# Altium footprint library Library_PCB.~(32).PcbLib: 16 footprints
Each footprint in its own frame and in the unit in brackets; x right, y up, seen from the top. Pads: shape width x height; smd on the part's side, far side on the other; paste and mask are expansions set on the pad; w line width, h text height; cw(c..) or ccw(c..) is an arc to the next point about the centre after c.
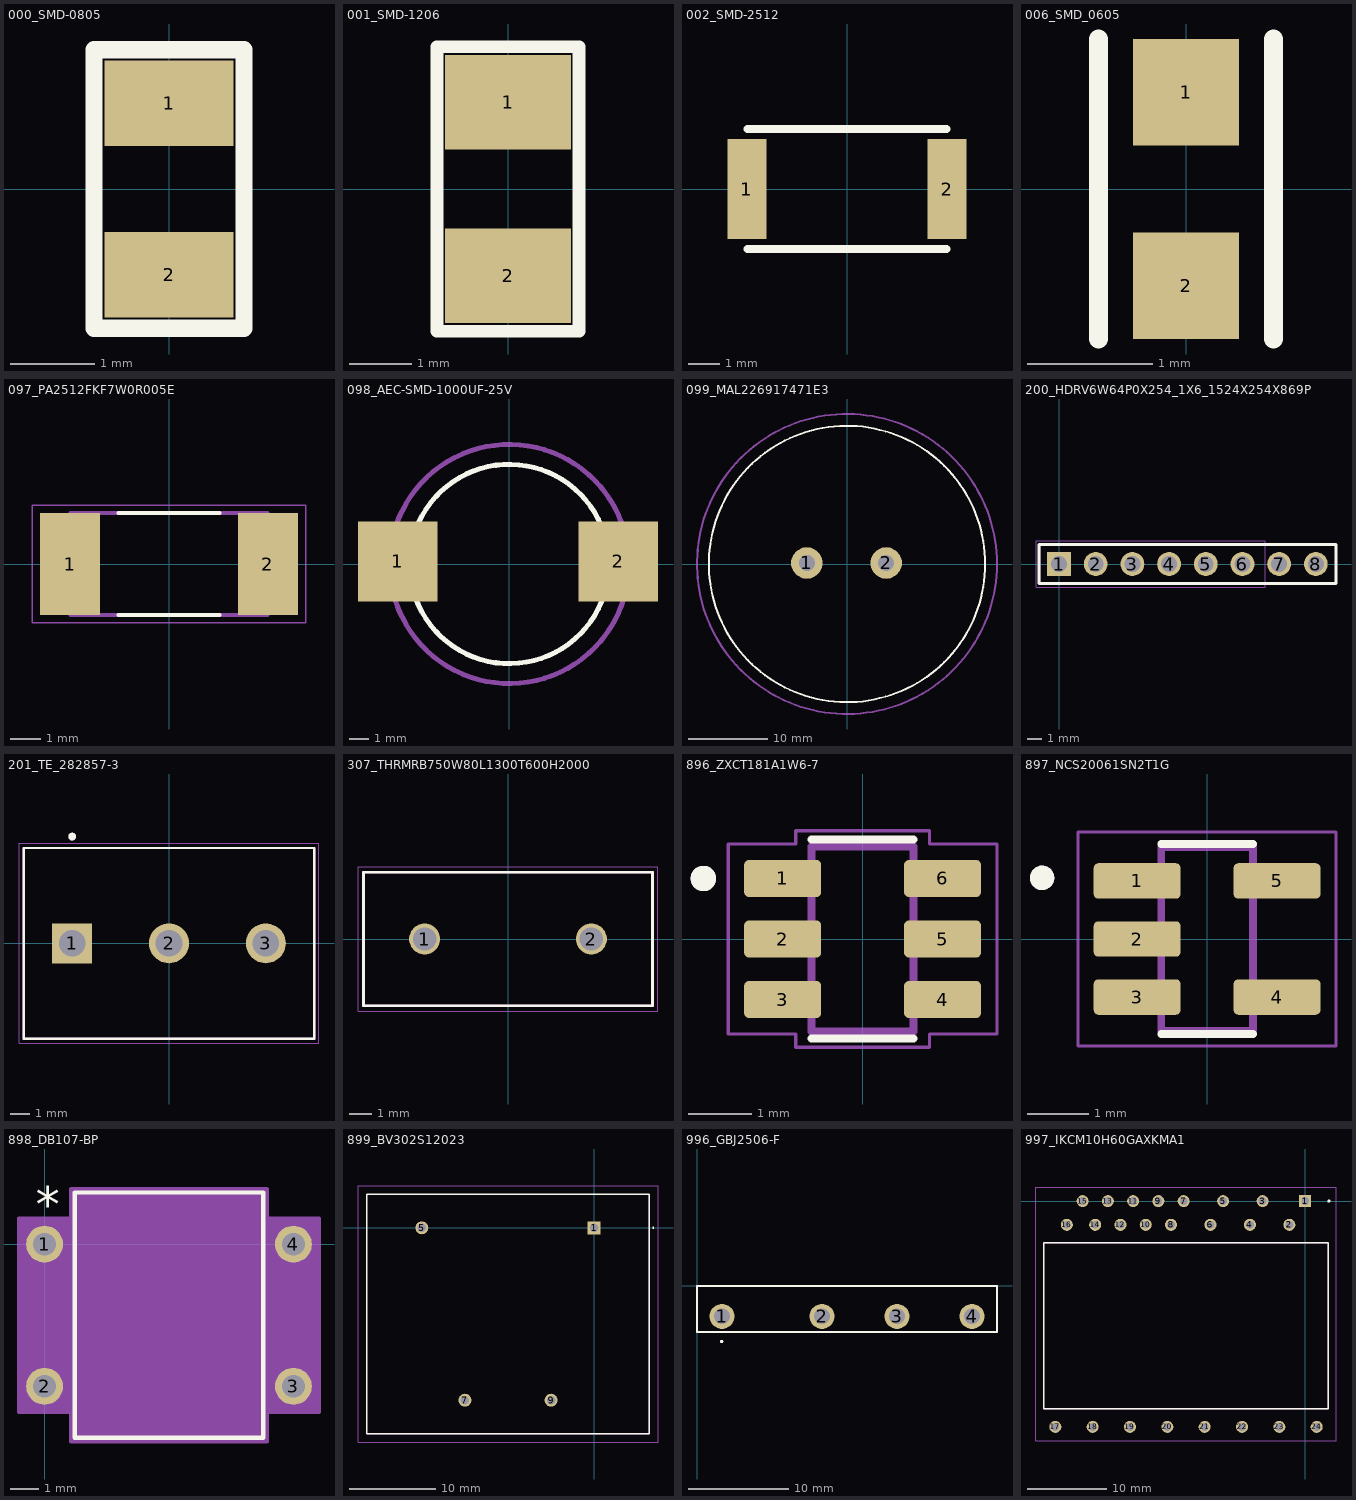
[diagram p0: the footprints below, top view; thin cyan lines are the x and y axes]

## 000_SMD-0805 [mil]
pads (2):
  rect 60x40 smd: 1(0,40) 2(0,-40)
Top Overlay:
  lines w8: -35,-65 35,-65 35,65 -35,65 -35,-65
3D body "SW3dPS-0805 SMD Resistor.STEP": height 30.79, standoff 0, extent -23.6,-39.36 25.6,39.38

## 001_SMD-1206 [mil]
pads (2):
  rect 80x60 smd: 1(0,55) 2(0,-55)
Top Overlay:
  lines w8: -45,-90 45,-90 45,90 -45,90 -45,-90
3D body "User Library-RES_3216-1206.step": height 33.46, standoff 0, extent -34.05,-65.94 34.06,65.95

## 002_SMD-2512 [mil]
pads (2):
  rect 49x125 smd: 1(-125.5,0) 2(125.5,0)
Top Overlay:
  lines w10: -125,-75 125,-75 ; -125,75 125,75
3D body "resistor 2512.step": height 63.07, standoff 0, extent -124.99,-59.05 125,59.06

## 006_SMD_0605 [mm]
pads (2):
  rect 0.85x0.85 smd: 1(0,0.775) 2(0,-0.775)
Top Overlay:
  lines w0.152: -0.7,-1.2 -0.7,1.2 ; 0.7,-1.2 0.7,1.2
3D body "0603.step": height 0.56, standoff 0, extent -0.4,-0.85 0.4,0.85

## 097_PA2512FKF7W0R005E [mm] "5 mΩ, 2 W, ±1% current-sense shunt resistor, 2512 (6332 metric) SMD package, low-resistance metal-element construction."
pads (2):
  rect 2x3.42 smd: 1(-3.302,0) 2(3.302,0)
Top Overlay:
  lines w0.127: -1.69,-1.7 1.69,-1.7 ; -1.69,1.7 1.69,1.7
Mechanical 13:
  lines w0.127: -3.3,-1.7 3.3,-1.7 3.3,1.7 -3.3,1.7 -3.3,-1.7
Mechanical 15:
  lines w0.05: -4.572,-1.958 4.572,-1.958 4.572,1.958 -4.572,1.958 -4.572,-1.958
3D body "step_temp.STEP": height 0.8, standoff 0, extent -3.2,-1.6 3.2,1.6

## 098_AEC-SMD-1000UF-25V [mm] "1000 µF, 25 V polarized aluminum electrolytic capacitor, SMD V-chip package, Ø10 mm body, approx. 10.5 mm height, 105 °C rated."
pads (2):
  rect 4x4 smd mask+0.12: 1(-5.588,0.127) 2(5.461,0.127)
Top Overlay:
  circle w0.254: c0,0 r5
Mechanical 15:
  circle w0.254: c0,0 r6
3D body: height 10, standoff 0, extent -5,-5 5,5

## 099_MAL226917471E3 [mm] "470 µF, 450 V polarized aluminum electrolytic capacitor, snap-in THT, Ø35 mm body, 10 mm lead spacing, 105 °C rated."
pads (2):
  round 4 hole 2 mask+0.05: 1(-5.08,0.127) 2(4.953,0.127)
Top Overlay:
  circle w0.254: c0,0 r17.5
Mechanical 15:
  circle w0.254: c0,0 r19
3D body: height 47, standoff 0, extent -17.5,-17.5 17.5,17.5

## 200_HDRV6W64P0X254_1X6_1524X254X869P [mm]
pads (8):
  rect 1.65x1.65 / inner round 1.65 / far side rect 1.65x1.65 hole 1.1: 1(0,0)
  round 1.65 hole 1.1: 2(2.54,0) 3(5.08,0) 4(7.62,0) 5(10.16,0) 6(12.7,0) 7(15.24,0) 8(17.78,0)
Top Overlay:
  lines w0.2: -1.397,-1.345 19.177,-1.345 19.177,1.345 -1.397,1.345 -1.397,-1.345
Mechanical 15:
  lines w0.1: -1.345,-1.345 19.177,-1.345 19.177,1.345 -1.345,1.345 -1.345,-1.345
Mechanical 20:
  lines w0.05: -1.595,-1.595 14.295,-1.595 14.295,1.595 -1.595,1.595 -1.595,-1.595
3D body "6130xx11121-6Pin.stp": height 8.69, standoff -3.2, extent 3.81,-1.27 19.05,1.27
3D body "6130xx11121-6Pin.stp": height 8.69, standoff -3.2, extent -1.27,-1.27 13.97,1.27

## 201_TE_282857-3 [mm]
pads (3):
  rect 2.1x2.1 / inner round 2.1 / far side rect 2.1x2.1 hole 1.4: 1(-5.08,0)
  round 2.1 hole 1.4: 2(0,0) 3(5.08,0)
Top Overlay:
  circle w0.2: c-5.08,5.6 r0.1
  lines w0.127: -7.62,-5 7.62,-5 7.62,5 -7.62,5 -7.62,-5
Mechanical 13:
  circle w0.2: c-5.08,5.6 r0.1
  lines w0.127: -7.62,-5 7.62,-5 7.62,5 -7.62,5 -7.62,-5
Mechanical 15:
  lines w0.05: -7.87,-5.25 7.87,-5.25 7.87,5.25 -7.87,5.25 -7.87,-5.25
3D body "step_temp.STEP": height 0, standoff -22.5, extent -8.12,-4.873 7.62,5.127

## 307_THRMRB750W80L1300T600H2000 [mm]
pads (2):
  round 1.4 hole 1.05: 1(-3.75,0) 2(3.75,0)
Top Overlay:
  lines w0.127: -6.5,-3 -6.5,3 6.5,3 6.5,-3 -6.5,-3
Mechanical 13:
  lines w0.127: -6.5,-3 6.5,-3 6.5,3 -6.5,3 -6.5,-3
Mechanical 15:
  lines w0.05: -6.75,-3.25 6.75,-3.25 6.75,3.25 -6.75,3.25 -6.75,-3.25

## 896_ZXCT181A1W6-7 [mm] "Bidirectional high-side current-sense amplifier, fixed gain 20 V/V, 2.7–5.5 V supply, up to 26 V common-mode input range, SOT-26 package."
pads (6):
  rrect25% 1.21x0.58 smd: 1(-1.255,0.95) 2(-1.255,0) 3(-1.255,-0.95) 4(1.255,-0.95) 5(1.255,0) 6(1.255,0.95)
Top Overlay:
  circle w0.2: c-2.5,0.95 r0.1
  lines w0.127: -0.8,-1.56 0.8,-1.56 ; -0.8,1.56 0.8,1.56
Mechanical 13:
  circle w0.2: c-2.5,0.95 r0.1
  lines w0.127: -0.8,-1.45 0.8,-1.45 0.8,1.45 -0.8,1.45 -0.8,-1.45
Mechanical 15:
  lines w0.05: -2.11,-1.49 -1.05,-1.49 -1.05,-1.7 1.05,-1.7 1.05,-1.49 2.11,-1.49 2.11,1.49 1.05,1.49 1.05,1.7 -1.05,1.7 -1.05,1.49 -2.11,1.49 -2.11,-1.49
3D body "step_temp.STEP": height 1.45, standoff 0, extent -1.4,-1.45 1.4,1.45

## 897_NCS20061SN2T1G [mm]
pads (5):
  rrect25% 1.42x0.58 smd: 1(-1.145,0.95) 2(-1.145,0) 3(-1.145,-0.95) 4(1.145,-0.95) 5(1.145,0.95)
Top Overlay:
  circle w0.2: c-2.7,1 r0.1
  lines w0.127: -0.75,-1.553 0.75,-1.553 ; -0.75,1.553 0.75,1.553
Mechanical 13:
  circle w0.2: c-2.7,1 r0.1
  lines w0.127: -0.75,-1.5 0.75,-1.5 0.75,1.5 -0.75,1.5 -0.75,-1.5
Mechanical 15:
  lines w0.05: -2.11,-1.75 2.11,-1.75 2.11,1.75 -2.11,1.75 -2.11,-1.75
3D body "step_temp.STEP": height 1.1, standoff 0, extent -1.375,-1.5 1.375,1.5

## 898_DB107-BP [mil]
pads (4):
  round 52 hole 32 paste-99999 mask+0: 1(0,0) 2(0,-200) 3(350,-200) 4(350,0)
Top Overlay:
  lines w6: 42.5,-272.5 307.5,-272.5 307.5,72.5 42.5,72.5 42.5,-272.5
  text "*" at -12.5,31 h50
Mechanical 13:
  lines w1: 163,67.5 ccw(c175,67.5) 187,67.5 ; -16,-216 -16,-184 47.5,-184 47.5,-216 -16,-216 ; -16,-16 -16,16 47.5,16 47.5,-16 -16,-16 ; 47.5,-267.5 302.5,-267.5 302.5,67.5 47.5,67.5 47.5,-267.5 ; 302.5,-216 302.5,-184 366,-184 366,-216 302.5,-216 ; 302.5,-16 302.5,16 366,16 366,-16 302.5,-16
  text "*" at 45,-25 h50
Mechanical 15:
  region: 312.5,-236 386,-236 386,36 312.5,36 312.5,77.5 37.5,77.5 37.5,36 -36,36 -36,-236 37.5,-236 37.5,-277.5 312.5,-277.5
  lines w6: -36,-236 -36,36 37.5,36 37.5,77.5 312.5,77.5 312.5,36 386,36 386,-236 312.5,-236 312.5,-277.5 37.5,-277.5 37.5,-236 -36,-236
3D body "DB-1_MCC.step": height 195.12, standoff -100, extent -10,-269.96 360,65

## 899_BV302S12023 [mm]
pads (4):
  rect 1.5x1.5 hole 1: 1(0,0)
  round 1.5 hole 1: 5(-20,0) 7(-15,-20) 9(-5,-20)
Top Overlay:
  lines w0.1: 6.8,0 cw(c6.85,0) 6.9,0 cw(c6.85,0) 6.8,0
  lines w0.2: -26.4,-23.9 -26.4,3.9 6.4,3.9 6.4,-23.9 -26.4,-23.9
Mechanical 15:
  lines w0.1: -26.4,-23.9 -26.4,3.9 6.4,3.9 6.4,-23.9 -26.4,-23.9
Mechanical 20:
  lines w0.1: -27.4,-24.9 -27.4,4.9 7.4,4.9 7.4,-24.9 -27.4,-24.9
3D body "BV302S12023.stp": height 29.79, standoff -4, extent -26.429,-23.876 6.362,3.912

## 996_GBJ2506-F [mm]
pads (4):
  round 2.5 hole 1.56: 1(2.5,-3.05) 2(12.5,-3.05) 3(20,-3.05) 4(27.5,-3.05)
Top Overlay:
  circle w0.2: c2.467,-5.567 r0.061
  lines w0.2: 0,-4.6 30,-4.6 30,0 0,0 0,-4.6
Mechanical 13:
  lines w0.2: 0,-4.6 0,0 30,0 30,-4.6 0,-4.6
3D body "GBJ2506-F.stp": height 25.23, standoff -13.07, extent -0.44,-4.69 29.86,0.11

## 997_IKCM10H60GAXKMA1 [mm]
pads (24):
  rect 1.524x1.524 hole 0.98: 1(0,0)
  round 1.524 hole 0.98: 2(-2,-3) 3(-5.4,0) 4(-7,-3) 5(-10.4,0) 6(-12,-3) 7(-15.4,0) 8(-17,-3) 9(-18.6,0) 10(-20.2,-3) 11(-21.8,0) 12(-23.4,-3) 13(-25,0) 14(-26.6,-3) 15(-28.2,0) 16(-30.2,-3) 17(-31.655,-28.6) 18(-26.925,-28.6) 19(-22.195,-28.6) 20(-17.465,-28.6) 21(-12.735,-28.6) 22(-8.005,-28.6) 23(-3.275,-28.6) 24(1.455,-28.6)
Top Overlay:
  lines w0.2: 2.9,0 ccw(c3,0) 3.1,0 ; 2.9,0 cw(c3,0) 3.1,0 ; 2.9,0 ccw(c3,0) 3.1,0 ; -33.1,-26.3 -33.1,-5.3 2.9,-5.3 2.9,-26.3 -33.1,-26.3
Mechanical 15:
  lines w0.1: -33.1,-26.3 -33.1,-5.3 2.9,-5.3 2.9,-26.3 -33.1,-26.3
Mechanical 20:
  lines w0.1: -34.1,-30.362 -34.1,1.762 3.9,1.762 3.9,-30.362 -34.1,-30.362
3D body "IKCM10H60GAXKMA1.stp": height 5.7, standoff -5, extent -33.079,-28.956 2.921,0.418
